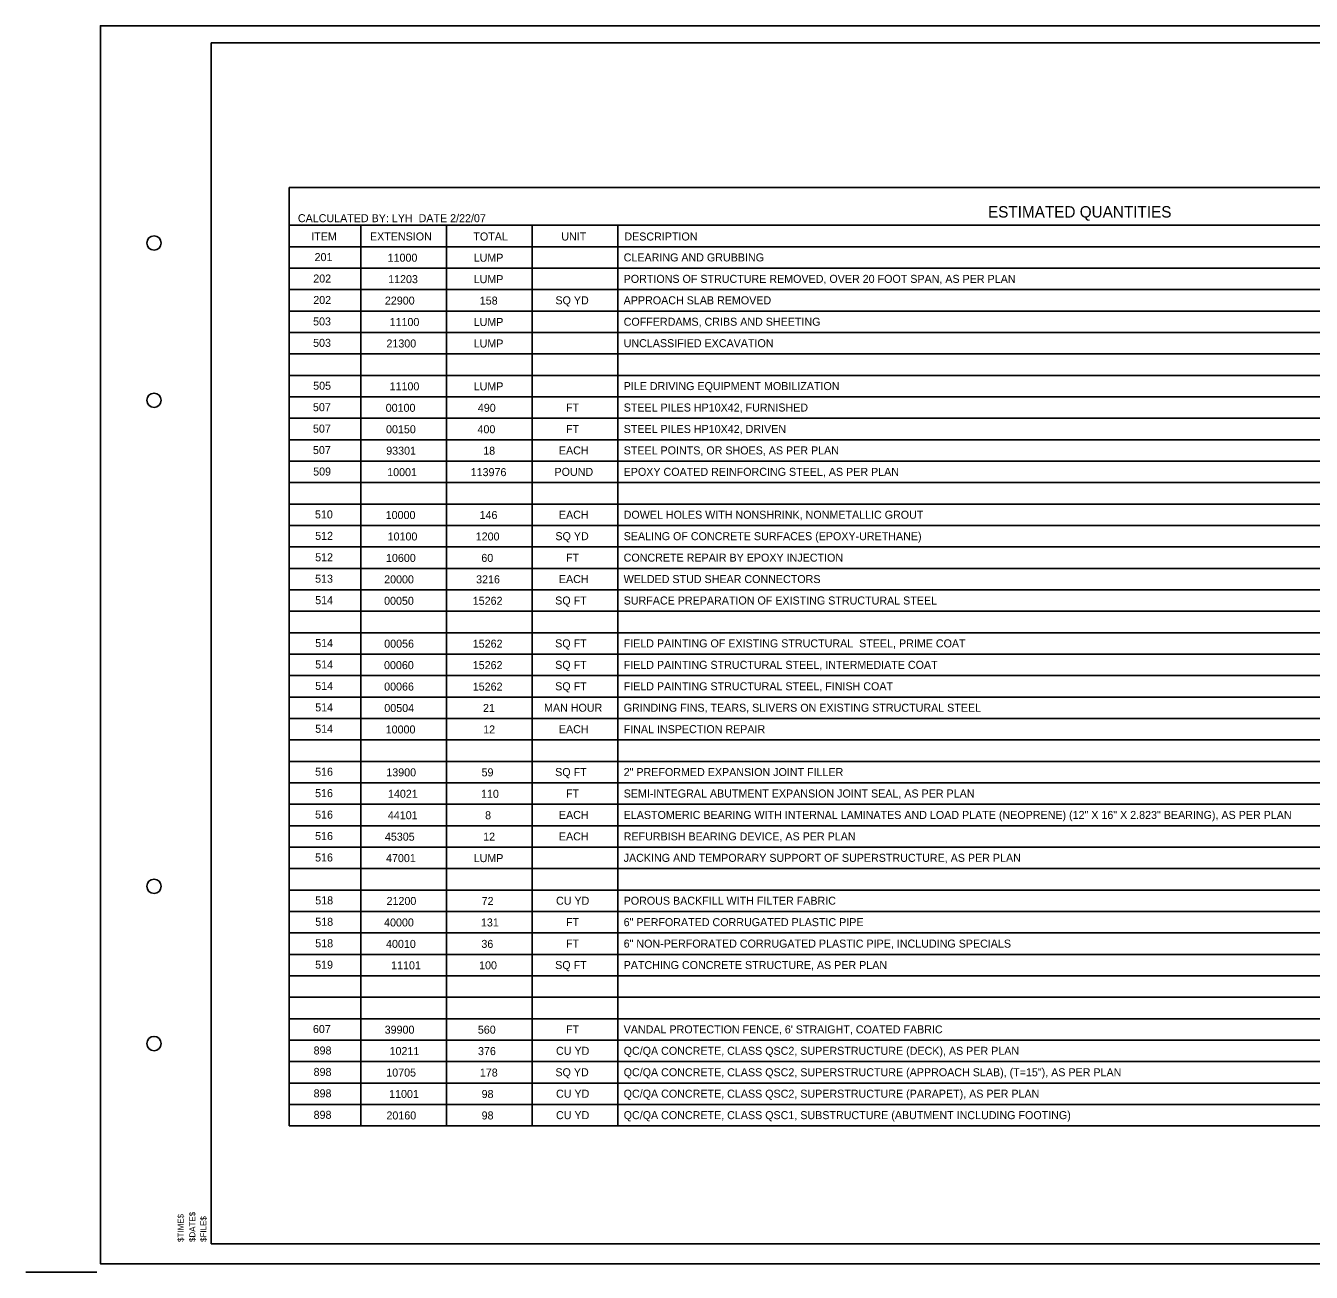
# Model space of a CAD drawing. Extents: x -70.8 to -34.9, y -11.1 to 10.9.
# Drawn here: x -70.82 to -48.33, y -11.14 to 10.66 of the extents above; entities that cross this region are included whole.
import ezdxf

# ---------------------------------------------------------------- set-up
doc = ezdxf.new("R2010")
doc.units = 0
for name, color, linetype in [('BR_P_Gen_Ground_Slope', 7, 'Continuous'), ('BR_P_Gen_Text', 7, 'Continuous'), ('BR_P_Prestress_Text', 7, 'Continuous'), ('Default', 7, 'Continuous'), ('SH_Border', 7, 'Continuous'), ('SH_Cut_Line', 7, 'Continuous')]:
    doc.layers.add(name, color=color, linetype=linetype)

msp = doc.modelspace()

# ---------------------------------------------------------------- linework, layer by layer
at = {"layer": 'BR_P_Gen_Ground_Slope'}
for p, q in [((-66.205, 7.824), (-38.5, 7.824)), ((-66.205, 7.824), (-66.205, -8.584)), ((-66.205, 7.166), (-38.5, 7.166)), ((-64.955, 7.166), (-64.955, -8.584)), ((-63.455, 7.166), (-63.455, -8.584)), ((-61.955, 7.166), (-61.955, -8.584)), ((-60.455, 7.166), (-60.455, -8.584)), ((-66.205, 6.791), (-38.5, 6.791)), ((-66.205, 6.416), (-38.5, 6.416)), ((-66.205, 6.041), (-38.5, 6.041)), ((-66.205, 5.666), (-38.5, 5.666)), ((-66.205, 5.291), (-38.5, 5.291)), ((-66.205, 4.916), (-38.5, 4.916)), ((-66.205, 4.541), (-38.5, 4.541)), ((-66.205, 4.166), (-38.5, 4.166)), ((-66.205, 3.791), (-38.5, 3.791)), ((-66.205, 3.416), (-38.5, 3.416)), ((-66.205, 3.041), (-38.5, 3.041)), ((-66.205, 2.666), (-38.5, 2.666)), ((-66.205, 2.291), (-38.5, 2.291)), ((-66.205, 1.916), (-38.5, 1.916)), ((-66.205, 1.541), (-38.5, 1.541)), ((-66.205, 1.166), (-38.5, 1.166)), ((-66.205, 0.791), (-38.5, 0.791)), ((-66.205, 0.416), (-38.5, 0.416)), ((-66.205, 0.041), (-38.5, 0.041)), ((-66.205, -0.334), (-38.5, -0.334)), ((-66.205, -0.709), (-38.5, -0.709)), ((-66.205, -1.084), (-38.5, -1.084)), ((-66.205, -1.459), (-38.5, -1.459)), ((-66.205, -1.834), (-38.5, -1.834)), ((-66.205, -2.209), (-38.5, -2.209)), ((-66.205, -2.584), (-38.5, -2.584)), ((-66.205, -2.959), (-38.5, -2.959)), ((-66.205, -3.334), (-38.5, -3.334)), ((-66.205, -3.709), (-38.5, -3.709)), ((-66.205, -4.084), (-38.5, -4.084)), ((-66.205, -4.459), (-38.5, -4.459)), ((-66.205, -4.834), (-38.5, -4.834)), ((-66.205, -5.209), (-38.5, -5.209)), ((-66.205, -5.584), (-38.5, -5.584)), ((-66.205, -5.959), (-38.5, -5.959)), ((-66.205, -6.334), (-38.5, -6.334)), ((-66.205, -6.709), (-38.5, -6.709)), ((-66.205, -7.084), (-38.5, -7.084)), ((-66.205, -7.459), (-38.5, -7.459)), ((-66.205, -7.834), (-38.5, -7.834)), ((-66.205, -8.209), (-38.5, -8.209)), ((-66.205, -8.584), (-38.5, -8.584))]:
    msp.add_line(p, q, dxfattribs=at)
at = {"layer": 'SH_Border'}
msp.add_lwpolyline([(-67.571, 10.356), (-36.071, 10.356), (-36.071, -10.644), (-67.571, -10.644)], close=True, dxfattribs=at)
for centre in [(-68.571, 6.856), (-68.571, 4.106), (-68.571, -4.394), (-68.571, -7.144)]:
    msp.add_circle(centre, 0.125, dxfattribs=at)
at = {"layer": 'SH_Cut_Line'}
msp.add_line((-69.571, -11.144), (-70.815, -11.144), dxfattribs=at)
msp.add_lwpolyline([(-35.509, -10.994), (-69.509, -10.994), (-69.509, 10.656), (-35.509, 10.656)], close=True, dxfattribs=at)

# ---------------------------------------------------------------- texts
at = {"layer": 'BR_P_Gen_Text'}
for s, height, p in [('ESTIMATED QUANTITIES', 0.2, (-53.982, 7.301)), ('CALCULATED BY: LYH  DATE 2/22/07', 0.14, (-66.054, 7.22)), ('ITEM', 0.14, (-65.821, 6.9)), ('EXTENSION', 0.14, (-64.793, 6.901)), ('TOTAL', 0.14, (-62.984, 6.9)), ('UNIT', 0.14, (-61.446, 6.9)), ('DESCRIPTION', 0.14, (-60.343, 6.9)), ('CLEARING AND GRUBBING', 0.14, (-60.355, 6.534)), ('PORTIONS OF STRUCTURE REMOVED, OVER 20 FOOT SPAN, AS PER PLAN', 0.14, (-60.355, 6.159)), ('SQ YD', 0.14, (-61.549, 5.784)), ('APPROACH SLAB REMOVED', 0.14, (-60.355, 5.784)), ('COFFERDAMS, CRIBS AND SHEETING', 0.14, (-60.355, 5.409)), ('UNCLASSIFIED EXCAVATION', 0.14, (-60.355, 5.034)), ('PILE DRIVING EQUIPMENT MOBILIZATION', 0.14, (-60.355, 4.284)), ('FT', 0.14, (-61.364, 3.909)), ('STEEL PILES HP10X42, FURNISHED', 0.14, (-60.355, 3.909)), ('FT', 0.14, (-61.364, 3.534)), ('STEEL PILES HP10X42, DRIVEN', 0.14, (-60.355, 3.534)), ('EACH', 0.14, (-61.488, 3.159)), ('STEEL POINTS, OR SHOES, AS PER PLAN', 0.14, (-60.355, 3.159)), ('POUND', 0.14, (-61.565, 2.784)), ('EPOXY COATED REINFORCING STEEL, AS PER PLAN', 0.14, (-60.355, 2.784)), ('EACH', 0.14, (-61.488, 2.034)), ('DOWEL HOLES WITH NONSHRINK, NONMETALLIC GROUT', 0.14, (-60.355, 2.034)), ('SQ YD', 0.14, (-61.549, 1.659)), ('SEALING OF CONCRETE SURFACES (EPOXY-URETHANE)', 0.14, (-60.355, 1.659)), ('FT', 0.14, (-61.364, 1.284)), ('CONCRETE REPAIR BY EPOXY INJECTION', 0.14, (-60.355, 1.284)), ('EACH', 0.14, (-61.488, 0.909)), ('WELDED STUD SHEAR CONNECTORS', 0.14, (-60.355, 0.909)), ('SQ FT', 0.14, (-61.553, 0.534)), ('SURFACE PREPARATION OF EXISTING STRUCTURAL STEEL', 0.14, (-60.355, 0.534)), ('SQ FT', 0.14, (-61.553, -0.216)), ('FIELD PAINTING OF EXISTING STRUCTURAL  STEEL, PRIME COAT', 0.14, (-60.355, -0.216)), ('SQ FT', 0.14, (-61.553, -0.591)), ('FIELD PAINTING STRUCTURAL STEEL, INTERMEDIATE COAT', 0.14, (-60.355, -0.591)), ('SQ FT', 0.14, (-61.553, -0.966)), ('FIELD PAINTING STRUCTURAL STEEL, FINISH COAT', 0.14, (-60.355, -0.966)), ('MAN HOUR', 0.14, (-61.748, -1.341)), ('GRINDING FINS, TEARS, SLIVERS ON EXISTING STRUCTURAL STEEL', 0.14, (-60.355, -1.341)), ('EACH', 0.14, (-61.488, -1.716)), ('FINAL INSPECTION REPAIR', 0.14, (-60.355, -1.716)), ('SQ FT', 0.14, (-61.553, -2.466)), ('2" PREFORMED EXPANSION JOINT FILLER', 0.14, (-60.355, -2.466)), ('FT', 0.14, (-61.364, -2.841)), ('SEMI-INTEGRAL ABUTMENT EXPANSION JOINT SEAL, AS PER PLAN', 0.14, (-60.355, -2.841)), ('EACH', 0.14, (-61.488, -3.216)), ('ELASTOMERIC BEARING WITH INTERNAL LAMINATES AND LOAD PLATE (NEOPRENE) (12" X 16" X 2.823" BEARING), AS PER PLAN', 0.14, (-60.355, -3.216)), ('EACH', 0.14, (-61.488, -3.591)), ('REFURBISH BEARING DEVICE, AS PER PLAN', 0.14, (-60.355, -3.591)), ('JACKING AND TEMPORARY SUPPORT OF SUPERSTRUCTURE, AS PER PLAN', 0.14, (-60.355, -3.966)), ('CU YD', 0.14, (-61.538, -4.716)), ('POROUS BACKFILL WITH FILTER FABRIC', 0.14, (-60.355, -4.716)), ('FT', 0.14, (-61.364, -5.091)), ('6" PERFORATED CORRUGATED PLASTIC PIPE', 0.14, (-60.355, -5.091)), ('FT', 0.14, (-61.364, -5.466)), ('6" NON-PERFORATED CORRUGATED PLASTIC PIPE, INCLUDING SPECIALS', 0.14, (-60.355, -5.466)), ('SQ FT', 0.14, (-61.553, -5.841)), ('PATCHING CONCRETE STRUCTURE, AS PER PLAN', 0.14, (-60.355, -5.841)), ('FT', 0.14, (-61.364, -6.966)), ("VANDAL PROTECTION FENCE, 6' STRAIGHT, COATED FABRIC", 0.14, (-60.355, -6.966)), ('QC/QA CONCRETE, CLASS QSC2, SUPERSTRUCTURE (DECK), AS PER PLAN', 0.14, (-60.355, -7.341)), ('CU YD', 0.14, (-61.538, -7.341)), ('SQ YD', 0.14, (-61.549, -7.716)), ('QC/QA CONCRETE, CLASS QSC2, SUPERSTRUCTURE (APPROACH SLAB), (T=15"), AS PER PLAN', 0.14, (-60.355, -7.716)), ('CU YD', 0.14, (-61.538, -8.091)), ('QC/QA CONCRETE, CLASS QSC2, SUPERSTRUCTURE (PARAPET), AS PER PLAN', 0.14, (-60.355, -8.091)), ('QC/QA CONCRETE, CLASS QSC1, SUBSTRUCTURE (ABUTMENT INCLUDING FOOTING)', 0.14, (-60.355, -8.466)), ('CU YD', 0.14, (-61.538, -8.466))]:
    msp.add_text(s, height=height, dxfattribs=at).set_placement(p)
at = {"layer": 'BR_P_Prestress_Text'}
for s, p in [('201', (-65.762, 6.54)), ('11000', (-64.484, 6.529)), ('LUMP', (-62.979, 6.529)), ('202', (-65.785, 6.165)), ('11203', (-64.475, 6.154)), ('LUMP', (-62.979, 6.154)), ('202', (-65.785, 5.79)), ('22900', (-64.532, 5.779)), ('158', (-62.872, 5.779)), ('503', (-65.788, 5.415)), ('11100', (-64.45, 5.404)), ('LUMP', (-62.979, 5.404)), ('503', (-65.788, 5.04)), ('21300', (-64.505, 5.029)), ('LUMP', (-62.979, 5.029)), ('505', (-65.787, 4.29)), ('11100', (-64.45, 4.279)), ('LUMP', (-62.979, 4.279)), ('507', (-65.79, 3.915)), ('00100', (-64.518, 3.904)), ('490', (-62.906, 3.904)), ('507', (-65.79, 3.54)), ('00150', (-64.512, 3.529)), ('400', (-62.912, 3.529)), ('507', (-65.79, 3.165)), ('93301', (-64.509, 3.154)), ('18', (-62.812, 3.154)), ('509', (-65.787, 2.79)), ('10001', (-64.492, 2.779)), ('113976', (-63.031, 2.779)), ('510', (-65.755, 2.04)), ('10000', (-64.518, 2.029)), ('146', (-62.876, 2.029)), ('512', (-65.752, 1.665)), ('10100', (-64.484, 1.654)), ('1200', (-62.943, 1.654)), ('512', (-65.752, 1.29)), ('10600', (-64.513, 1.279)), ('60', (-62.845, 1.279)), ('513', (-65.753, 0.915)), ('20000', (-64.545, 0.904)), ('3216', (-62.936, 0.904)), ('514', (-65.751, 0.54)), ('00050', (-64.546, 0.529)), ('15262', (-62.995, 0.529)), ('514', (-65.751, -0.21)), ('00056', (-64.544, -0.221)), ('15262', (-62.995, -0.221)), ('514', (-65.751, -0.585)), ('00060', (-64.547, -0.596)), ('15262', (-62.995, -0.596)), ('514', (-65.751, -0.96)), ('00066', (-64.545, -0.971)), ('15262', (-62.995, -0.971)), ('514', (-65.751, -1.335)), ('00504', (-64.542, -1.346)), ('21', (-62.816, -1.346)), ('514', (-65.751, -1.71)), ('10000', (-64.518, -1.721)), ('12', (-62.813, -1.721)), ('516', (-65.753, -2.46)), ('13900', (-64.507, -2.471)), ('59', (-62.841, -2.471)), ('516', (-65.753, -2.835)), ('14021', (-64.478, -2.846)), ('110', (-62.85, -2.846)), ('516', (-65.753, -3.21)), ('44101', (-64.48, -3.221)), ('8', (-62.779, -3.221)), ('516', (-65.753, -3.585)), ('45305', (-64.532, -3.596)), ('12', (-62.813, -3.596)), ('516', (-65.753, -3.96)), ('47001', (-64.512, -3.971)), ('LUMP', (-62.979, -3.971)), ('518', (-65.75, -4.71)), ('21200', (-64.503, -4.721)), ('72', (-62.84, -4.721)), ('518', (-65.75, -5.085)), ('40000', (-64.546, -5.096)), ('131', (-62.852, -5.096)), ('518', (-65.75, -5.46)), ('40010', (-64.512, -5.471)), ('36', (-62.844, -5.471)), ('519', (-65.752, -5.835)), ('11101', (-64.423, -5.846)), ('100', (-62.884, -5.846)), ('607', (-65.791, -6.96)), ('39900', (-64.536, -6.971)), ('560', (-62.906, -6.971)), ('898', (-65.779, -7.335)), ('10211', (-64.45, -7.346)), ('376', (-62.903, -7.346)), ('898', (-65.779, -7.71)), ('10705', (-64.508, -7.721)), ('178', (-62.871, -7.721)), ('898', (-65.779, -8.085)), ('11001', (-64.458, -8.096)), ('98', (-62.84, -8.096)), ('898', (-65.779, -8.46)), ('20160', (-64.505, -8.471)), ('98', (-62.84, -8.471))]:
    msp.add_text(s, height=0.14, dxfattribs=at).set_placement(p)
at = {"layer": 'Default'}
for s, p in [('$DATE$', (-67.849, -10.614)), ('$TIME$', (-68.053, -10.614)), ('$FILE$', (-67.654, -10.613))]:
    msp.add_text(s, height=0.1043, rotation=90.0067, dxfattribs=at).set_placement(p)

doc.saveas('drawing.dxf')
